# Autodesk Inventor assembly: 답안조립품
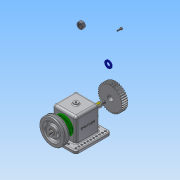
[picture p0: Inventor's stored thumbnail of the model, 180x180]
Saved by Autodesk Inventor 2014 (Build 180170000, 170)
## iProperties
Created: 2018-11
Part Number: 답안조립품
Document SubType Name: Assembly
Designer: user
Author: user
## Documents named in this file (13)
- C:\Users\user\Desktop\481107V1018\답안조립품.iam
- C:\Users\user\Desktop\481107V1018\본체.ipt
- C:\Users\user\Desktop\481107V1018\V벨트풀리.ipt
- C:\Users\user\Desktop\481107V1018\너트 M12x1.25.ipt
- C:\Users\user\Desktop\481107V1018\베어링 6203.ipt
- C:\Users\user\Desktop\481107V1018\볼트 M4.ipt
- C:\Users\user\Desktop\481107V1018\부시.ipt
- C:\Users\user\Desktop\481107V1018\스퍼기어.ipt
- C:\Users\user\Desktop\481107V1018\오일 실 26 38 8.ipt
- C:\Users\user\Desktop\481107V1018\와셔 12x24.ipt
- C:\Users\user\Desktop\481107V1018\축.ipt
- C:\Users\user\Desktop\481107V1018\커버.ipt
- C:\Users\user\Desktop\481107V1018\키 5x5x12.ipt
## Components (1 placed, 1 different names)
1. V벨트풀리:1
